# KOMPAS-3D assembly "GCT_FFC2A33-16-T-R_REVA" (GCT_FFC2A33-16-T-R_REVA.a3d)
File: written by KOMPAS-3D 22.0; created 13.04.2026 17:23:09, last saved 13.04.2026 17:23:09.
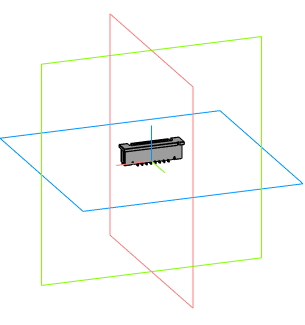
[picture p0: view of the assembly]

Document properties: Автор: Andrey; Полное имя файла: C:\Users\User1\Documents\GCT_FFC2A33-16-T-R_REVA.a3d

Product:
- Component [detail]: 1-1734742-6  | qty 1  | source file: 1-1734742-6.m3d
- Part/product: GCT_FFC2A33-16-T-R_REVA
    Комментарий: GCT_FFC2A33-16-T-R_REVA

Referenced files in C:\Users\User1\Documents\: 1-1734742-6.m3d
